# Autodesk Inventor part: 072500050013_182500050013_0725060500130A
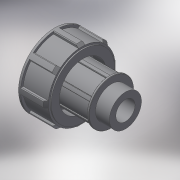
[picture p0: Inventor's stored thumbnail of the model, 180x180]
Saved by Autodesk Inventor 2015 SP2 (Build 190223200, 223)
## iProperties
Created: 2017-04
Part Number: 072500050013_182500050013_0725060500130A
Material: Generic
Description: PLASSON THREADED ADAPTOR 50-1.1/4"
Document SubType Name: Modeling
Designer: KIM
Density: 1 g/cm^3
Appearance: Default
Author: KIM
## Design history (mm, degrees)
derived "07250.ipt"
feature "Solid1::07250.ipt"
tag "TaggingFeature1"
body "Solid1"
other parameters: "d1" = 41.91, "d2" = 104, "d3" = 24, "d6" = 96, "d7" = 89.28, "d8" = 76.8, "d10" = 58.674, "d12" = 25.146, "d13" = 33.528, "d14" = 27.6, "d15" = 72, "d16" = 3.12, "d17" = 41.6, "d18" = 24, "d19" = 28.8, "d24" = 8.382, "d25" = 4.191, "d27" = 0, "d28" = 3.3528, "d31" = 0.8382, "d35" = 360 deg, "d41" = 29.337, "d56" = 55, "d57" = 5, "d58" = 2.5, "d60" = 0, "d61" = 0.4191, "d64" = 0.4191, "d68" = 360 deg, "R_" = 41.91, "E_" = 96, "H_" = 104, "l_2" = 24
